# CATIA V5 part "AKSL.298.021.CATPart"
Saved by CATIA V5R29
Part number: АКСЛ.298.021
Definition: Перемычка
Publications: "Грань по длине шипа", "Грань по ширине шипа", "Грань по ширине Extract.5", "Грань по длине Extract.4"
Material "Steel": density 7860 kg/m3, Young's modulus 2e+11 Pa, Poisson ratio 0.266, thermal expansion 1.17e-05 1/K
Bounding box of the stored display mesh (mm): x 50 to 227.673, y -233.378 to -50, z 37 to 40
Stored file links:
  Z:\ООО Аксель\Соединения бруса\Соединения бруса\Соединения из листа\АКСЛ.298.020 (Дуо)\AKSL.298.021.CATPart
  Z:\ООО Аксель\Соединения бруса\Соединения бруса\Соединения из листа\АКСЛ.298.020 (Дуо)\AKSL.298.020.CATProduct
  Z:\ООО Аксель\Соединения бруса\Соединения бруса\Соединения из листа\АКСЛ.298.020 (Дуо)\AKSL.298.020.Skelet.CATPart
  Z:\#Catalog_GosNIIAS\Holes&Pockets\Part\Соединение шип-паз\Ship-Paz.CATPart
  Z:\ООО Аксель\Соединения бруса\Соединения бруса\Соединения из листа\АКСЛ.298.030 (Трио)\AKSL.298.030.CATProduct
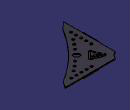
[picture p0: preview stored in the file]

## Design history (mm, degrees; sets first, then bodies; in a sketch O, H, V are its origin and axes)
SheetMetalParameters1: Thickness 3, BendRadius 4, KFactor 0.356492 {= log(min(100,max(20*SheetMetalParameters1.BendRadius,SheetMetalParameters1.Thickness)/SheetMetalParameters1.Thickness))/log(100)/2}, ReliefRadialLength 1, ReliefAxialLength 2, MinimumBendRadius 0
Set1 "Шип в центре грани"
  Extract1 "Плоскость шипа": ExtractElem face of Wall1
  Extract2 "Грань по длине шипа": ExtractElem edge of Extract1
  Extract3 "Грань по ширине шипа": ExtractElem edge of Extract1
Set2
  DatumCurve1: linked copy from another document
  DatumCurve2: linked copy from another document
  Plane1: linked copy from another document
Set3
  Extract4 "Грань по длине Extract.4": ExtractElem edge [face of SHM_Mirror1 | face of SHM_Mirror1]
  Extract5 "Грань по ширине Extract.5": ExtractElem edge [face of SHM_Mirror1 | face of SHM_Mirror1]
  Plane2: type Between, Element1 face of Recognize1, Element2 face of Recognize1, Ratio 0.5
Body1 (main body)
  Pad1: profile DatumCurve2, length 3
  Pocket1: profile DatumCurve1, through (limit type 6)
  Recognize1: KFacteur 0.356492 {= SheetMetalParameters1.KFactor}, Recognize_BendTable SheetMetalParameters1, Recognize_ReferenceFace end face of Pad1, Recognize_BendDefaultRadius 4
  Wall1: Thickness 3, Profile Sketch1, ListTangentTo face of Recognize1, OffsetValue 0
  Sketch1 on face of Recognize1, origin (39, 0, 37), H (0, -1, 0), V (-1, 0, 0)
    reference projected line E1 (52, -188.6727) -> (52, -31.2496) from edge [face of Recognize1 | face of Recognize1]
    line L1 (50, -84.9612) -> (52, -84.9612)
    line L2 (52, -84.9612) -> (52, -134.9612)
    line L3 (52, -134.9612) -> (50, -134.9612)
    line L4 (50, -134.9612) -> (50, -84.9612)
    axis line L5 (52, -109.9612) -> (50, -109.9612)
    point P7 (52, -109.9612)
    point P8 (50, -109.9612)
    distance L2 L4 = 2
    distance L1 L3 = 50
    length E1 = 157.4231 (reference)
    perpendicularity: L2 L1
    midpoint: P7 L2, P8 L4, P7 E1
    coincidence: L2 E1
  SHM_Mirror1: MirroringPlane Plane1, ObjectToMirror Wall1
